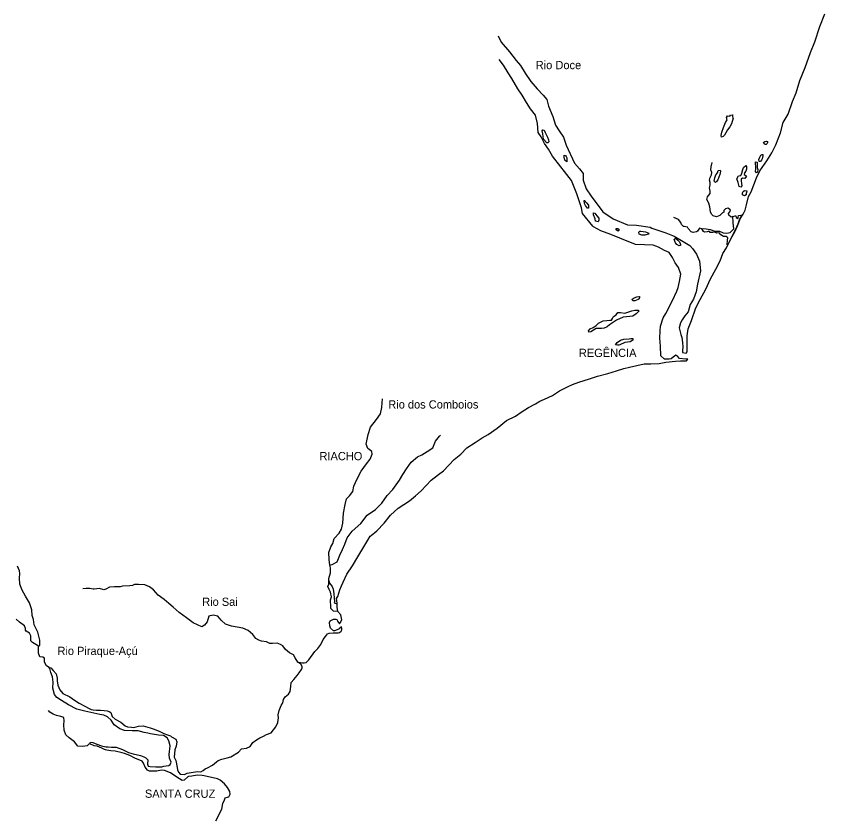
# Model space of a CAD drawing. Extents: x 662444 to 1640468, y 7452018 to 9606170.
# Drawn here: x 993275 to 1056574, y 7783209 to 7846194 of the extents above; entities that cross this region are included whole.
import ezdxf

# ---------------------------------------------------------------- set-up
doc = ezdxf.new("R2010")
doc.units = 0
doc.layers.add('Level 1', color=7, linetype='Continuous')
doc.layers.add('Level 3', color=7, linetype='Continuous')

msp = doc.modelspace()

# ---------------------------------------------------------------- linework, layer by layer
at = {"layer": 'Level 1'}
for points in [[(1031009, 7844654), (1031227, 7844170), (1031900, 7843394), (1032407, 7842735), (1032764, 7842325), (1033126, 7841736), (1033570, 7841079), (1034049, 7840509), (1034518, 7840006), (1034803, 7839665), (1034956, 7839138), (1035281, 7838351), (1035503, 7837666), (1035784, 7837225), (1036106, 7836715), (1036320, 7836098), (1036973, 7834689), (1037371, 7834255), (1037655, 7833880), (1037660, 7833358), (1037903, 7832673), (1038296, 7832094), (1039197, 7830867), (1040013, 7830332), (1041136, 7829854), (1041831, 7829833), (1042901, 7829678), (1043035, 7829607), (1044141, 7829240), (1044786, 7828987), (1045345, 7828648), (1045996, 7828251), (1046220, 7828010), (1046523, 7827557), (1046769, 7827016), (1046841, 7826269), (1046620, 7825220), (1046496, 7824624), (1046300, 7824052), (1046044, 7823616), (1045880, 7823054), (1045606, 7822729), (1045418, 7822424), (1045264, 7822195), (1045178, 7821786), (1045299, 7821272), (1045387, 7821047), (1045437, 7820645), (1045448, 7820289), (1045441, 7820056), (1045446, 7819878), (1045717, 7819803), (1045805, 7819923), (1045796, 7820312), (1045790, 7821168), (1045870, 7821721), (1046132, 7822368), (1046479, 7823369), (1046804, 7824026), (1047261, 7824823), (1047633, 7825634), (1048035, 7826388), (1048372, 7827056), (1048589, 7827616), (1048887, 7828062), (1049224, 7828763), (1049526, 7829309), (1049763, 7829824), (1049936, 7830330), (1050190, 7830700), (1050347, 7831018), (1050444, 7831437), (1050611, 7832076), (1050812, 7832437), (1051008, 7832998), (1051215, 7833547), (1051495, 7834094), (1052025, 7834867), (1052423, 7835499), (1052737, 7836112), (1053103, 7837056), (1053318, 7837872), (1053707, 7838516), (1054043, 7839516), (1054338, 7840185), (1054610, 7841155), (1055032, 7842187), (1055458, 7843351), (1055790, 7844186), (1056195, 7845385), (1056574, 7846384)], [(1033924, 7815838), (1034278, 7816061), (1034630, 7816228), (1035270, 7816509), (1035817, 7816859), (1036491, 7817217), (1036821, 7817351), (1037322, 7817536), (1038161, 7817799), (1038778, 7818025), (1039595, 7818234), (1040254, 7818425), (1040828, 7818608), (1041294, 7818727), (1042439, 7818970), (1042955, 7818976), (1043608, 7819001), (1044127, 7819107), (1044898, 7819184), (1045278, 7819205), (1045752, 7819224), (1045861, 7819354), (1045693, 7819359), (1045210, 7819396), (1045027, 7819613), (1044912, 7819650), (1044708, 7819512), (1044546, 7819372), (1044387, 7819344), (1044029, 7819355), (1043743, 7819619), (1043724, 7820375), (1043658, 7820977), (1043675, 7821554), (1043719, 7821942), (1043928, 7822591), (1044117, 7822908), (1044653, 7823936), (1044991, 7824659), (1045085, 7824967), (1045194, 7825430), (1045306, 7825994), (1045122, 7826522), (1044859, 7826885), (1044661, 7827302), (1044389, 7827700), (1044025, 7827844), (1043549, 7828125), (1043142, 7828260), (1042448, 7828303), (1041754, 7828324), (1040525, 7828805), (1039818, 7829093), (1039047, 7829394), (1038457, 7829712), (1038426, 7829757), (1037593, 7830749), (1037532, 7831184), (1037165, 7832295), (1036742, 7833319), (1036206, 7834046), (1035911, 7834399), (1035262, 7835240), (1034941, 7835794), (1034627, 7836215), (1034369, 7836745), (1034126, 7837096), (1034073, 7837787), (1033935, 7838457), (1033539, 7838947), (1033226, 7839434), (1032885, 7840021), (1032552, 7840509), (1032081, 7841323), (1031788, 7841765), (1031416, 7842353), (1031092, 7842796)], [(1048948, 7837294), (1048825, 7837065), (1048714, 7836868), (1048605, 7836772), (1048499, 7836730), (1048450, 7836854), (1048500, 7837119), (1048637, 7837471), (1048797, 7837877), (1048929, 7838073), (1048872, 7838275), (1048949, 7838383), (1049150, 7838377), (1049184, 7838454), (1049321, 7838483), (1049342, 7838483), (1049349, 7838338), (1049367, 7838248), (1049387, 7838215), (1049268, 7837763), (1049145, 7837544), (1048948, 7837294)], [(1034492, 7836974), (1034456, 7837209), (1034490, 7837285), (1034606, 7837282), (1034685, 7837091), (1034784, 7836877), (1034874, 7836718), (1034952, 7836527), (1034958, 7836360), (1034892, 7836273), (1034818, 7836276), (1034543, 7836562), (1034492, 7836974)], [(1051784, 7836308), (1051881, 7836382), (1052019, 7836400), (1052092, 7836387), (1052090, 7836309), (1052056, 7836222), (1051980, 7836146), (1051906, 7836148), (1051834, 7836206), (1051784, 7836308)], [(1036176, 7835158), (1036180, 7835302), (1036274, 7835277), (1036336, 7835219), (1036385, 7835107), (1036379, 7834907), (1036386, 7834785), (1036232, 7834912), (1036176, 7835158)], [(1051496, 7835161), (1051575, 7835325), (1051671, 7835355), (1051713, 7835354), (1051710, 7835254), (1051661, 7835033), (1051615, 7834913), (1051528, 7834826), (1051444, 7834829), (1051416, 7834963), (1051496, 7835161)], [(1049362, 7830503), (1049235, 7830474), (1049050, 7830624), (1049043, 7830758), (1049141, 7830866), (1049178, 7831042), (1048992, 7831159), (1048801, 7831121), (1048661, 7830992), (1048656, 7830847), (1048560, 7830806), (1048451, 7830698), (1048343, 7830601), (1048098, 7830498), (1047837, 7830572), (1047714, 7830698), (1047614, 7830868), (1047563, 7831281), (1047498, 7831561), (1047338, 7831843), (1047397, 7832053), (1047594, 7832302), (1047590, 7832502), (1047545, 7832770), (1047604, 7832969), (1047600, 7833169), (1047553, 7833370), (1047601, 7833569), (1047713, 7833776), (1047740, 7833953), (1047662, 7834178), (1047669, 7834400), (1047743, 7834742)], [(1051319, 7834199), (1051302, 7833989), (1051216, 7833925), (1051156, 7834038), (1051183, 7834237), (1051168, 7834426), (1051143, 7834627), (1051148, 7834794), (1051273, 7834768), (1051279, 7834623), (1051271, 7834356), (1051319, 7834199)], [(1048197, 7833395), (1048087, 7833243), (1048011, 7833178), (1047920, 7833292), (1047959, 7833536), (1048040, 7833777), (1048161, 7833940), (1048229, 7834116), (1048388, 7834134), (1048418, 7834077), (1048392, 7833911), (1048346, 7833790), (1048197, 7833395)], [(1049792, 7833179), (1049695, 7833471), (1049829, 7833701), (1050008, 7833717), (1050077, 7833893), (1050160, 7834191), (1050217, 7834355), (1050391, 7834506), (1050451, 7834426), (1050445, 7834226), (1050388, 7834072), (1050289, 7833942), (1050253, 7833810), (1050346, 7833740), (1050439, 7833682), (1050307, 7833497), (1050128, 7833503), (1050031, 7833428), (1050016, 7833295), (1050053, 7833105), (1050068, 7832927), (1050012, 7832806), (1049876, 7832855), (1049792, 7833179)], [(1050141, 7832202), (1050125, 7832358), (1050192, 7832478), (1050288, 7832542), (1050467, 7832514), (1050432, 7832404), (1050429, 7832315), (1050426, 7832204), (1050286, 7832131), (1050141, 7832202)], [(1038065, 7831401), (1038082, 7831279), (1038079, 7831168), (1037984, 7831171), (1037843, 7831375), (1037764, 7831544), (1037728, 7831756), (1037791, 7831754), (1037852, 7831663), (1037923, 7831583), (1038065, 7831401)], [(1038887, 7830377), (1038893, 7830221), (1038837, 7830089), (1038617, 7830152), (1038591, 7830341), (1038464, 7830645), (1038479, 7830789), (1038573, 7830786), (1038735, 7830559), (1038887, 7830377)], [(1046942, 7829555), (1046764, 7829605), (1046620, 7829365), (1046534, 7829301), (1046259, 7829265), (1046113, 7829314), (1045889, 7829565), (1045818, 7829667), (1045557, 7829742), (1045515, 7829743), (1045361, 7829892), (1045292, 7830050), (1045110, 7830278), (1044767, 7830444)], [(1049371, 7829092), (1049293, 7828928), (1049169, 7828687), (1049023, 7828391), (1048978, 7828293), (1048926, 7828294), (1048968, 7828660), (1048985, 7828848), (1048851, 7828941), (1048640, 7828948), (1048444, 7829087), (1048312, 7829224), (1048090, 7829209), (1047987, 7829290), (1047807, 7829251), (1047607, 7829257), (1047546, 7829337), (1047441, 7829351), (1047366, 7829320), (1047165, 7829282), (1047072, 7829351), (1046942, 7829555), (1047089, 7829562), (1047289, 7829556), (1047593, 7829491), (1047957, 7829357), (1048126, 7829375), (1048326, 7829357), (1048617, 7829237), (1048901, 7829206), (1049176, 7829253), (1049449, 7829556), (1049400, 7830013), (1049405, 7830202), (1049379, 7830370), (1049362, 7830503), (1049543, 7830576), (1049606, 7830574), (1049634, 7830440), (1049769, 7830369), (1049792, 7830446), (1049818, 7830590), (1050008, 7830628), (1050125, 7830647), (1050102, 7830603), (1050004, 7830484), (1049893, 7830298), (1049776, 7829924), (1049663, 7829683), (1049561, 7829431), (1049371, 7829092)], [(1040281, 7829435), (1040210, 7829537), (1040253, 7829569), (1040359, 7829566), (1040452, 7829530), (1040451, 7829474), (1040449, 7829430), (1040385, 7829376), (1040281, 7829435)], [(1042542, 7829311), (1042791, 7829204), (1042737, 7829139), (1042481, 7829046), (1042239, 7829054), (1042042, 7829137), (1042004, 7829283), (1042101, 7829358), (1042175, 7829356), (1042542, 7829311)], [(1045163, 7828209), (1044998, 7828325), (1044897, 7828462), (1044778, 7828710), (1044875, 7828807), (1045071, 7828657), (1045204, 7828530), (1045263, 7828406), (1045282, 7828328), (1045280, 7828250), (1045163, 7828209)], [(1041950, 7824029), (1041704, 7823903), (1041546, 7823908), (1041487, 7824054), (1041649, 7824160), (1041851, 7824232), (1042020, 7824260), (1042073, 7824259), (1042071, 7824192), (1042046, 7824071), (1041950, 7824029)], [(1041800, 7822889), (1041552, 7822719), (1041320, 7822682), (1040781, 7822642), (1040258, 7822391), (1040032, 7822243), (1039721, 7822041), (1039548, 7821880), (1039312, 7821764), (1039080, 7821738), (1038828, 7821746), (1038670, 7821751), (1038455, 7821624), (1038251, 7821474), (1038103, 7821468), (1038085, 7821568), (1038196, 7821732), (1038451, 7821824), (1038677, 7821984), (1038851, 7822156), (1039235, 7822345), (1039500, 7822381), (1039753, 7822407), (1039879, 7822403), (1039957, 7822523), (1040035, 7822676), (1040239, 7822814), (1040371, 7822999), (1040581, 7822993), (1040917, 7822938), (1041470, 7823121), (1041714, 7823192), (1041872, 7823187), (1041956, 7823184), (1042038, 7823126), (1041800, 7822889)], [(1040537, 7820472), (1040441, 7820453), (1040346, 7820444), (1040178, 7820461), (1040321, 7820656), (1040590, 7820837), (1040834, 7820907), (1041266, 7820928), (1041383, 7820969), (1041542, 7820975), (1041548, 7820841), (1041344, 7820703), (1040921, 7820638), (1040537, 7820472)], [(1017748, 7802032), (1017752, 7802176), (1017870, 7802628), (1017882, 7803017), (1017825, 7803218), (1017775, 7803664), (1017738, 7804209), (1017898, 7804649), (1018063, 7804911), (1018159, 7805297), (1018550, 7805730), (1018748, 7806035), (1018857, 7806520), (1018890, 7807286), (1019016, 7807982), (1019133, 7808412), (1019371, 7808638), (1019634, 7808975), (1019709, 7809394), (1019978, 7809975), (1020280, 7810588), (1020707, 7811154), (1020991, 7811512), (1021150, 7811907), (1021125, 7812119), (1020795, 7812362), (1020668, 7812699), (1020838, 7813460), (1021001, 7814011), (1021482, 7814630), (1021790, 7815065), (1021909, 7815561), (1021920, 7815928), (1021961, 7816237)], [(1011797, 7789333), (1012076, 7789547), (1012354, 7789694), (1012631, 7789842), (1012866, 7789957), (1013237, 7790102), (1013608, 7790568), (1013765, 7790908), (1013797, 7791274), (1013794, 7791518), (1013866, 7791838), (1014014, 7792234), (1014136, 7792452), (1014196, 7792695), (1014338, 7792902), (1014587, 7793128), (1014729, 7793323), (1014783, 7793722), (1014813, 7794043), (1015008, 7794259), (1015270, 7794574), (1015434, 7794791), (1015599, 7795042), (1015666, 7795195), (1015669, 7795295), (1015569, 7795476), (1015332, 7795616), (1015520, 7795600), (1015688, 7795572), (1015814, 7795569), (1015983, 7795608), (1016188, 7795802), (1016660, 7796466), (1016877, 7796704), (1017128, 7797019), (1017308, 7797413), (1017493, 7797641), (1017635, 7797837), (1017785, 7797910), (1018079, 7797913), (1018352, 7797916), (1018478, 7797912), (1018584, 7797942), (1018704, 7798061), (1018759, 7798148), (1018773, 7798292), (1018734, 7798382), (1018649, 7798340), (1018561, 7798232), (1018402, 7798159), (1018189, 7798076), (1018126, 7798078), (1017890, 7798285), (1017833, 7798475), (1017809, 7798731), (1017855, 7798863), (1018121, 7798989), (1018290, 7798995), (1018404, 7798947), (1018432, 7798835), (1018594, 7798619), (1018649, 7798696), (1018761, 7798937), (1018678, 7799339), (1018465, 7799590), (1018401, 7799936), (1018409, 7800191), (1018411, 7800258), (1018358, 7800604), (1018446, 7800756), (1018599, 7801285), (1018744, 7801603), (1018869, 7801899), (1019161, 7802524), (1019589, 7803167), (1020020, 7803865), (1020795, 7805175), (1020983, 7805492), (1021068, 7805534), (1021510, 7805920), (1022074, 7806504), (1022577, 7807144), (1023172, 7807693), (1024072, 7808255), (1024536, 7808653), (1024989, 7809050), (1025760, 7809872), (1026331, 7810310), (1026729, 7810609), (1027565, 7811484), (1028093, 7811902), (1028560, 7812399), (1029193, 7812825), (1029751, 7813186), (1030222, 7813460), (1030921, 7813940), (1031644, 7814540), (1032369, 7814885), (1032810, 7815194), (1033379, 7815566), (1033924, 7815838)], [(1017825, 7803218), (1018005, 7803280), (1018390, 7803479), (1018615, 7803995), (1018828, 7804444), (1019008, 7804861), (1019180, 7805356), (1019564, 7805889), (1020265, 7806479), (1020747, 7807142), (1021391, 7807590), (1021890, 7808086), (1022328, 7808684), (1022752, 7809150), (1023288, 7809867), (1023554, 7810314), (1023841, 7810773), (1024204, 7811295), (1024689, 7811692), (1025041, 7811870), (1025459, 7812113), (1025878, 7812412), (1026103, 7812916), (1026420, 7813318), (1026496, 7813393)], [(995026, 7796887), (995122, 7796939), (995123, 7797350), (994962, 7797977), (994684, 7798551), (994633, 7798963), (994526, 7799288), (994497, 7799733), (994323, 7800282), (994011, 7800790), (993741, 7801253), (993565, 7801747), (993547, 7802213), (993556, 7802557), (993541, 7802780), (993391, 7803133)], [(1015332, 7795616), (1015121, 7795956), (1014991, 7796193), (1014671, 7796369), (1014363, 7796622), (1014140, 7796906), (1013954, 7797023), (1013704, 7797108), (1013336, 7797085), (1013136, 7797091), (1012867, 7797210), (1012490, 7797276), (1012261, 7797349), (1012034, 7797489), (1011812, 7797807), (1011443, 7798117), (1011017, 7798285), (1010128, 7798444), (1009670, 7798602), (1009311, 7798912), (1009058, 7799230), (1008692, 7799319), (1008364, 7799239), (1008225, 7798788), (1008008, 7798528), (1007804, 7798389), (1007130, 7798719), (1006616, 7799101), (1006040, 7799528), (1005568, 7799941), (1005219, 7800229), (1004870, 7800539), (1004386, 7800864), (1004019, 7801285), (1003721, 7801516), (1003358, 7801670), (1002844, 7801718), (1002550, 7801715), (1002379, 7801620), (1002168, 7801604), (1001600, 7801587), (1001409, 7801526), (1000978, 7801527), (1000578, 7801505), (1000300, 7801335), (1000131, 7801284), (999798, 7801405), (999376, 7801339), (999302, 7801330), (999041, 7801382), (998747, 7801390), (998494, 7801364)], [(1018465, 7799590), (1018118, 7799611), (1017894, 7799829), (1017901, 7800095), (1017888, 7800351), (1017892, 7800506), (1017962, 7800737), (1017868, 7801107), (1017779, 7801309), (1017681, 7801545), (1017739, 7801721), (1017748, 7802032), (1017805, 7801819), (1018007, 7801547), (1018096, 7801344), (1018148, 7800965), (1018193, 7800364), (1018169, 7800265), (1018409, 7800191)], [(995851, 7795220), (995655, 7795348), (995485, 7795641), (995491, 7795841), (995493, 7795930), (995369, 7796011), (995139, 7796051), (995011, 7796332), (995021, 7796698), (995026, 7796887), (994933, 7796945), (994561, 7797155), (994428, 7797292), (994413, 7797515), (994429, 7797681), (994330, 7797894), (994061, 7798068), (994000, 7798137), (994004, 7798270), (993915, 7798461), (993524, 7798761), (993275, 7798996)], [(1005319, 7787610), (1005398, 7787797), (1005271, 7788122), (1005248, 7788412), (1005341, 7789087), (1005236, 7789467), (1005106, 7789693), (1004796, 7789880), (1004409, 7789924), (1003802, 7790019), (1003593, 7790059), (1003301, 7790111), (1002822, 7790247), (1002349, 7790261), (1001762, 7790278), (1001377, 7790422), (1000945, 7790723), (1000713, 7791085), (1000426, 7791337), (1000136, 7791468), (999822, 7791521), (999123, 7791685), (998643, 7791788), (998017, 7791939), (997376, 7792301), (996829, 7792639), (996468, 7792871), (996264, 7793099), (996152, 7793590), (996165, 7794056), (996114, 7794480), (995997, 7794816), (995912, 7795130), (995851, 7795220), (995986, 7795172), (996170, 7794967), (996404, 7794716), (996479, 7794370), (996483, 7794158), (996537, 7793835), (996694, 7793453), (996939, 7793180), (997467, 7792909), (997848, 7792654), (998199, 7792411), (998695, 7792153), (998934, 7792035), (999141, 7791929), (999308, 7791891), (999570, 7791884), (999864, 7791864), (1000167, 7791833), (1000387, 7791816), (1000544, 7791767), (1000678, 7791685), (1000795, 7791371), (1001020, 7791154), (1001455, 7790930), (1001814, 7790654), (1001980, 7790571), (1002294, 7790529), (1002493, 7790523), (1002842, 7790613), (1003211, 7790636), (1003753, 7790498), (1004086, 7790389), (1004511, 7790199), (1004781, 7790080), (1005051, 7789961), (1005352, 7789853), (1005445, 7789783), (1005775, 7789596), (1005843, 7789394), (1005791, 7789051), (1005699, 7788754), (1005659, 7788478), (1005640, 7788190), (1005780, 7787941), (1005890, 7787383), (1005916, 7787193), (1005985, 7787025), (1006106, 7786866), (1006442, 7786845), (1006654, 7786928), (1006961, 7786996), (1007467, 7787060), (1007729, 7787052), (1007900, 7787147), (1008061, 7787276), (1008263, 7787359), (1008647, 7787570), (1008948, 7787816), (1009088, 7787923), (1009375, 7788037), (1009788, 7788147), (1010084, 7788228), (1010672, 7788577), (1010921, 7788836), (1011312, 7788903), (1011588, 7789028), (1011797, 7789333)], [(999043, 7789233), (998958, 7789202), (998839, 7789084), (998470, 7789016), (998093, 7789060), (997850, 7789389), (997418, 7789701), (997152, 7789931), (997036, 7790312), (997016, 7790712), (997026, 7791045), (997012, 7791301), (996762, 7791375), (996428, 7791462), (996168, 7791547), (995910, 7791709), (995798, 7791846)], [(1008909, 7783208), (1009377, 7784117), (1009452, 7784559), (1009577, 7784855), (1009644, 7785020), (1009813, 7785059), (1009930, 7785078), (1010030, 7785286), (1010005, 7785498), (1009825, 7785825), (1009592, 7786098), (1009232, 7786386), (1009036, 7786492), (1007992, 7786722), (1007836, 7786760), (1007448, 7786771), (1007036, 7786706), (1006773, 7786680), (1006709, 7786659), (1006429, 7786390), (1006281, 7786372), (1005858, 7786617), (1005363, 7786954), (1004886, 7787156), (1004624, 7787175), (1004286, 7787096), (1003886, 7787085), (1003708, 7787090), (1003553, 7787172), (1003370, 7787411), (1003253, 7787714), (1003132, 7787873), (1002572, 7788122), (1002168, 7788334), (1001762, 7788467), (1001575, 7788528), (1001033, 7788655), (1000687, 7788698), (1000363, 7788729), (1000259, 7788766), (1000196, 7788790), (999979, 7788896), (999616, 7789051), (999385, 7789068), (999043, 7789233), (999099, 7789354), (999288, 7789349), (999589, 7789218), (999963, 7789085), (1000297, 7788998), (1000475, 7788993), (1000748, 7788985), (1001115, 7788963), (1001604, 7788794), (1002080, 7788558), (1002444, 7788448), (1003008, 7788310), (1003257, 7788214), (1003423, 7788131), (1003576, 7787982), (1003566, 7787649), (1003614, 7787482), (1003760, 7787455), (1004201, 7787442), (1004526, 7787433), (1004673, 7787429), (1004843, 7787491), (1005022, 7787519), (1005212, 7787536), (1005319, 7787610)]]:
    msp.add_lwpolyline(points, dxfattribs=at)

# ---------------------------------------------------------------- texts
at = {"layer": 'Level 3'}
for s, height, p in [('Rio Doce', 646.6, (1033946, 7842045)), ('REGÊNCIA', 645.8, (1037322, 7819516)), ('Rio dos Comboios', 645.56, (1022402, 7815482)), ('RIACHO', 645.3, (1017017, 7811438)), ('Rio Sai', 644.8, (1007838, 7800036)), ('Rio Piraque-Açú', 644.61, (996509, 7796190)), ('SANTA CRUZ', 644.3, (1003354, 7785012))]:
    msp.add_text(s, height=height, dxfattribs=at).set_placement(p)

doc.saveas('drawing.dxf')
